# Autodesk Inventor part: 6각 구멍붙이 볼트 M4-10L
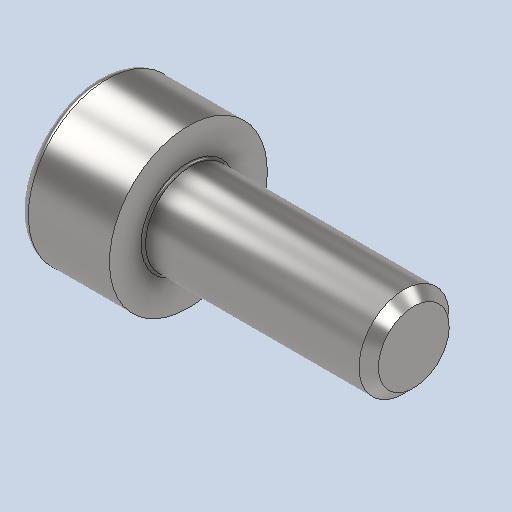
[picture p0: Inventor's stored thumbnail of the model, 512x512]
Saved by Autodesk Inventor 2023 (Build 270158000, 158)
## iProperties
Created: 2025-04
Part Number: 6각 구멍붙이 볼트 M4-10L
Material: 강철, 연강
Description: 6각머리 태핑 나사
Document SubType Name: Modeling
Designer: Admin
Mass: 2.0371 g
Surface Area: 3.0572 cm^2
Volume: 0.259174 cm^3
Density: 7.86 g/cm^3
Appearance: 기본값
Sending System: Autodesk Inventor 2026
Preprocessor: ST-DEVELOPER v20.1
Author: jhkim
Revision Number: 1
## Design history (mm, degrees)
feature "Solid1"
node "솔리드1"
